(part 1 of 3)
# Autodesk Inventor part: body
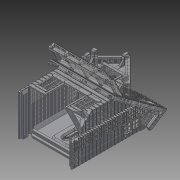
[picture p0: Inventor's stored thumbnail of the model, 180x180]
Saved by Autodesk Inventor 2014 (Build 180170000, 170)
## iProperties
Created: 2013-07
Part Number: body
Material: Generic
Document SubType Name: Modeling
Designer: Brent J. Rosenburgh
Density: 1 g/cm^3
Appearance: Default
Author: Brent J. Rosenburgh
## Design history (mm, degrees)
sketch "Sketch1"
  geometry: L1 (0, 0)-(-140, 0); L2 (-140, 0)-(-140, -200); L3 (-140, -200)-(0, -200); L4 (0, -200)-(0, 0)
  constraints: 8 end point, 2 parallel, 1 horizontal, 1 perpendicular
extrude "Extrusion1" new body sketch "Sketch1" distance "d1" = 140; taper "d2" = 0 deg
sketch "Sketch2"
  geometry: L1 (0, 0)-(0, 200) reference; L2 (0, 200)-(-140, 200) reference; L3 (-140, 0)-(-140, 200) reference; L4 (-22, 200)-(0, 166); L5 (-22, 200)-(-88, 108); L6 (-88, 108)-(-140, 84)
  constraints: 6 end point, 3 point on line
extrude "Extrusion2" cut sketch "Sketch2" distance "d3" = 140; taper "d4" = 0 deg
sketch "Sketch3"
  geometry: L1 (52, 108)-(0, 84) reference; L2 (0, 0)-(0, 84) reference; L3 (140, 0)-(0, 0) reference; L4 (0, 84)-(4, 75.333); L5 (4, 75.333)-(48.778, 96); L6 (48.778, 96)-(48.778, 10); L7 (48.778, 10)-(0, 10); 1 further point
  constraints: 8 end point, 4 perpendicular, 1 point on line
extrude "Extrusion3" cut sketch "Sketch3" distance "d5" = 140; taper "d6" = 0 deg
sketch "Sketch4"
  geometry: L1 (48.778, 10)-(0, 10) reference; L2 (0, 0)-(0, 10) reference; L3 (140, 0)-(0, 0) reference; L4 (140, 0)-(140, 166) reference; L5 (140, 166)-(118, 200) reference; L6 (118, 200)-(52, 108) reference; L7 (48.778, 96)-(48.778, 10) reference; L8 (140, 149.481)-(117.478, 184.288); L9 (117.478, 184.288)-(48.778, 88.524); 1 further point
  constraints: 4 end point, 2 parallel, 2 point on line
extrude "Extrusion4" cut sketch "Sketch4" distance "d7" = 126; taper "d8" = 0 deg
sketch "Sketch5"
  geometry: L1 (140, 10)-(91.222, 10) reference; L2 (91.222, 10)-(91.222, 96) reference; L3 (88, 108)-(22, 200) reference; L4 (22, 200)-(0, 166) reference; L5 (0, 166)-(0, 0) reference; L6 (0, 0)-(140, 0) reference; L7 (140, 10)-(140, 0) reference; L8 (0, 149.465)-(22.527, 184.279); L9 (22.527, 184.279)-(91.222, 88.522); 1 further point
  constraints: 4 end point, 2 parallel, 2 point on line
extrude "Extrusion5" cut sketch "Sketch5" distance "d9" = 10; taper "d10" = 0 deg
sketch "Sketch6"
  geometry: L1 (0, 10)-(48.778, 10) reference; L2 (0, 0)-(0, 10) reference; L3 (140, 0)-(0, 0) reference; L4 (140, 149.481)-(140, 0) reference; L5 (117.478, 184.288)-(140, 149.481) reference; L6 (48.778, 10)-(136, 10); L7 (136, 10)-(136, 155.663); 1 further point
  constraints: 4 end point, 2 perpendicular, 1 point on line
  dimensions: "d11" = 87.222 distance of L1.end L6.end
extrude "Extrusion6" join sketch "Sketch6" distance "d12" = 116; taper "d13" = 0 deg
sketch "Sketch7"
  geometry: L1 (136, 10)-(0, 10) reference; L2 (136, 155.663)-(136, 10) reference; L3 (136, 10)-(48.778, 10); L4 (48.778, 10)-(48.778, 93); L5 (48.778, 93)-(118, 189); L6 (118, 189)-(136, 163); L7 (136, 163)-(136, 155.663); L8 (136, 155.663)-(136, 10); 1 further point
  constraints: 12 end point, 3 perpendicular, 1 point on line
  dimensions: "d14" = 87.222 distance of L1.start L3.end
extrude "Extrusion7" join sketch "Sketch7" distance "d15" = 4; taper "d16" = 0 deg
sketch "Sketch8"
  geometry: L1 (-88, -41.481)-(-140, -65.481) reference; L2 (-140, -65.481)-(-136, -74.148) reference; L3 (-136, -74.148)-(-91.222, -53.481) reference; L4 (-91.222, -60.958)-(-22.522, 34.807) reference; L5 (-88, -41.481)-(-99.275, -57.198); 1 further point
  constraints: 2 end point, 1 parallel, 1 point on line
extrude "Extrusion8" cut sketch "Sketch8" distance "d17" = 16; taper "d18" = 0 deg
sketch "Sketch9"
  geometry: L1 (91.222, -53.465)-(136, -74.131) reference; L2 (136, -74.131)-(140, -65.465) reference; L3 (140, -65.465)-(88, -41.465) reference; L4 (88, -41.465)-(22, 50.535) reference; L5 (88, -41.465)-(99.275, -57.181); 1 further point
  constraints: 2 end point, 1 collinear, 1 point on line
extrude "Extrusion9" cut sketch "Sketch9" distance "d19" = 16; taper "d20" = 0 deg
sketch "Sketch10"
  geometry: L1 (22.527, 34.814)-(91.222, -60.943) reference; L2 (91.222, -60.943)-(91.222, -53.465) reference; L3 (91.222, -53.465)-(99.275, -57.181) reference; L4 (99.275, -57.181)-(105.601, -66); L5 (91.222, -60.943)-(98.503, -71.092); L6 (98.503, -71.092)-(105.601, -66); 1 further point
  constraints: 6 end point, 2 parallel
extrude "Extrusion10" join sketch "Sketch10" distance "d21" = 140; taper "d22" = 0 deg
sketch "Sketch11"
  geometry: L1 (0, 140)-(0, 0) reference; L2 (120, 140)-(120, 0) reference; L3 (0, 140)-(120, 140) reference; L4 (0, 91)-(13, 91); L5 (13, 91)-(13, 133); L6 (120, 91)-(107, 91); L7 (107, 91)-(107, 133); L8 (107, 133)-(13, 133); 1 further point
  constraints: 10 end point, 3 perpendicular, 2 parallel, 2 point on line
extrude "Extrusion11" cut sketch "Sketch11" distance "d23" = 10; taper "d24" = 0 deg
sketch "Sketch12"
  geometry: L1 (13, 0)-(0, 0) reference; L2 (13, 10)-(13, 0) reference; L3 (13, 10)-(9, 10) reference; L4 (0, 10)-(9, 10) reference; L5 (0, 0)-(0, 10) reference; 1 further point
extrude "Extrusion12" join sketch "Sketch12" distance "d25" = 0.22222; taper "d26" = 0 deg
sketch "Sketch13"
  geometry: L1 (13, 0)-(0, 0) reference; L2 (13, 0)-(13, 10) reference; L3 (4, 10)-(13, 10) reference; L4 (4, 10)-(0, 10) reference; L5 (0, 0)-(0, 10) reference; 1 further point
extrude "Extrusion13" join sketch "Sketch13" distance "d27" = 0.22222; taper "d28" = 0 deg
sketch "Sketch14"
  geometry: L1 (38, 139)-(74, 139); L2 (74, 139)-(74, 103); L3 (74, 103)-(38, 103); L4 (38, 103)-(38, 139); L5 (38, 139)-(74, 103); L6 (74, 139)-(38, 103); 2 further points
  constraints: 12 end point, 2 midpoint, 2 parallel, 1 horizontal, 1 perpendicular
extrude "Extrusion14" cut sketch "Sketch14" distance "d29" = 127.97222; taper "d30" = 0 deg
sketch "Sketch15"
  geometry: L1 (36, 0)-(36, -10.75) reference; L2 (0, -10.75)-(-16, -10.75); L3 (-16, -10.75)-(-16, 40); L4 (52.035, 40)-(52.035, -10.75); L5 (52.035, -10.75)-(36, -10.75); L6 (36, -10.75)-(36, -5.375); L7 (36, -5.375)-(46.252, -5.375); L8 (46.252, -5.375)-(46.252, 40); L9 (46.252, 40)-(52.035, 40); L10 (0, -5.375)-(-10, -5.375); L11 (-10, -5.375)-(-10, 40); L12 (-10, 40)-(-16, 40); L13 (0, -5.375)-(0, -10.75); 1 further point
  constraints: 24 end point, 5 perpendicular, 4 parallel, 1 collinear, 1 midpoint
extrude "Extrusion15" join sketch "Sketch15" distance "d31" = 42; taper "d32" = 0 deg
sketch "Sketch16"
  geometry: L1 (16.035, 0)-(16.035, 42) reference; L2 (0, 0)-(0, 42) reference; L3 (16.035, 35.983)-(-51.983, 35.983); L4 (-51.983, 35.983)-(-51.983, 41.983); L5 (-51.983, 41.983)-(-17.983, 76); L6 (-17.983, 76)-(16.035, 42); L7 (16.035, 35.983)-(16.035, 42); 1 further point
  constraints: 10 end point, 3 perpendicular, 1 collinear, 1 point on line
extrude "Extrusion16" join sketch "Sketch16" distance "d33" = 5.375; taper "d34" = 0 deg
sketch "Sketch17"
  geometry: L1 (62.217, 34.508)-(56.252, 34.508) reference; L2 (62.217, 34.508)-(28.235, 68.508) reference; L3 (28.235, 68.508)-(-5.783, 34.508) reference; L4 (0, 34.508)-(-5.783, 34.508) reference; L5 (0, 34.508)-(28.14, 62.634); L6 (28.14, 62.634)-(56.252, 34.508); 1 further point
  constraints: 4 end point, 1 parallel, 1 perpendicular
extrude "Extrusion17" join sketch "Sketch17" distance "d35" = 52.875; taper "d36" = 0 deg
sketch "Sketch18"
  geometry: L1 (-15.076, -36)-(-25.826, -36) reference; L2 (10.75, 0)-(-15.076, -36) reference; L3 (10.75, 0)-(0, 0) reference; L4 (-20.451, -28.508)-(0, 0) reference; L5 (-20.451, -28.508)-(-20.451, -36); 1 further point
  constraints: 2 end point, 1 midpoint
extrude "Extrusion18" cut sketch "Sketch18" distance "d37" = 10; taper "d38" = 0 deg
sketch "Sketch19"
  geometry: L1 (10.75, 0)-(31.201, -28.508) reference; L2 (0, 0)-(10.75, 0) reference; L3 (25.826, -36)-(0, 0) reference; L4 (25.826, -36)-(36.576, -36) reference; L5 (31.201, -28.508)-(31.201, -36); 1 further point
  constraints: 2 end point, 1 midpoint
extrude "Extrusion19" cut sketch "Sketch19" distance "d39" = 10.25211; taper "d40" = 0 deg
sketch "Sketch20"
  geometry: L1 (9.87, 42)-(14.174, 36) reference; L2 (0, 42)-(9.87, 42) reference; L3 (0, 0)-(0, 42) reference; L4 (0, 0)-(40, 0) reference; L5 (24.924, 36)-(20.62, 42) reference; L6 (14.174, 36)-(40, 0); L7 (9.87, 42)-(-9.5, 69); L8 (-9.5, 69)-(-9.5, 37); L9 (-9.5, 37)-(0, 37); 1 further point
  constraints: 8 end point, 2 perpendicular, 1 collinear, 1 parallel, 1 point on line
extrude "Extrusion20" cut sketch "Sketch20" distance "d41" = 66.7521; taper "d43" = 0 deg; dims "d42" = 7.376, "d44" = 0
sketch "Sketch21"
  geometry: L1 (0, 0)-(56.252, 0) reference; L2 (56.252, 0)-(56.252, 7.384) reference; L3 (56.252, 7.384)-(28.112, 41.999) reference; L4 (28.112, 41.999)-(0, 7.384) reference; L5 (0, 7.384)-(0, 0) reference; 1 further point
extrude "Extrusion21" cut sketch "Sketch21" distance "d45" = 11.2479; taper "d46" = 0 deg
sketch "Sketch22"
  geometry: L1 (-52, 42)-(-51.965, 42) reference; L2 (16.035, 42)-(-17.983, 76) reference; L3 (-17.983, 76)-(-51.965, 42) reference; L4 (-17.994, 64.072)-(-65.969, 16.072); L5 (-17.994, 64.072)-(30.031, 16.072); L6 (16.035, 42)-(36, 22.045); L7 (36, 22.045)-(30.031, 16.072); L8 (-52, 42)-(-71.945, 22.045); L9 (-71.945, 22.045)-(-65.969, 16.072); 1 further point
  constraints: 12 end point, 3 parallel, 3 perpendicular
extrude "Extrusion22" join sketch "Sketch22" distance "d47" = 33.7521; taper "d48" = 0 deg
sketch "Sketch23"
  geometry: L1 (-10.252, 35.841)-(-10.252, 39.402) reference; L2 (-10.252, 35.841)-(17.994, 64.072) reference; L3 (17.994, 64.072)-(46, 36.052) reference; L4 (46, 39.402)-(46, 36.052) reference; L5 (40.954, 47.048)-(46, 39.402) reference; L6 (17.888, 70.126)-(40.954, 47.048) reference; L7 (-5.201, 47.048)-(17.888, 70.126) reference; L8 (-10.252, 39.402)-(-5.201, 47.048) reference; 1 further point
extrude "Extrusion23" cut sketch "Sketch23" distance "d49" = 28.3771; taper "d50" = 0 deg
sketch "Sketch24"
  geometry: L1 (0, 0)-(-26.478, 36.908) reference; L2 (-23.002, 39.402)-(5.375, 39.402) reference; L3 (-26.478, 36.908)-(-26.478, 12); L4 (-26.478, 12)-(-8.609, 12); 1 further point
  constraints: 4 end point, 2 perpendicular, 1 point on line
extrude "Extrusion24" cut sketch "Sketch24" distance "d51" = 83.1271; taper "d53" = 0 deg; dims "d52" = 26.189, "d54" = 0
sketch "Sketch25"
  geometry: L1 (36, 22.045)-(-17.983, 76) reference; L2 (-17.983, 76)-(-51.965, 42) reference; L3 (-52, 42)-(-51.965, 42) reference; L4 (-52, 42)-(-71.945, 22.045) reference; L5 (-71.945, 22.045)-(-65.969, 16.072) reference; L6 (-65.969, 16.072)-(-52, 30.049) reference; L7 (16.035, 30.061)-(30.031, 16.072) reference; L8 (30.031, 16.072)-(36, 22.045) reference; L9 (-52, 30.049)-(-17.994, 64.072); L10 (-17.994, 64.072)-(16.035, 30.061); 1 further point
  constraints: 4 end point, 1 parallel, 1 perpendicular
extrude "Extrusion25" join sketch "Sketch25" distance "d55" = 10; taper "d56" = 0 deg
sketch "Sketch26"
  geometry: L1 (46, -10.75)-(10, -10.75) reference; L2 (24, -10.75)-(24, -72); L3 (32, -10.75)-(32, -72); L4 (32, -72)-(24, -72); 1 further point
  constraints: 6 end point, 2 perpendicular, 2 point on line, 1 parallel
extrude "Extrusion26" join sketch "Sketch26" distance "d57" = 8; taper "d58" = 0 deg
sketch "Sketch27"
  geometry: L1 (57.663, -5)-(51.163, -8) reference; L2 (61.25, 0)-(57.663, -5) reference; L3 (51.163, -8)-(0, -8) reference; L4 (25.582, -8)-(35.339, -15); L5 (35.339, -15)-(36.733, -16); L6 (36.733, -16)-(29.367, -19.4); L7 (29.367, -19.4)-(13.476, -8); L8 (25.582, -8)-(13.476, -8); 1 further point
  constraints: 10 end point, 2 collinear, 2 parallel, 1 midpoint, 1 perpendicular, 1 point on line
extrude "Extrusion27" join sketch "Sketch27" distance "d59" = 7; taper "d60" = 0 deg
sketch "Sketch28"
  geometry: L1 (13.476, -8)-(0, -8) reference; L2 (13.476, -8)-(28.23, -18.584) reference; L3 (35.596, -15.185)-(28.23, -18.584) reference; L4 (35.596, -15.185)-(25.582, -8) reference; L5 (25.582, -8)-(13.476, -8); 1 further point
  constraints: 2 end point, 1 collinear
extrude "Extrusion28" cut sketch "Sketch28" distance "d61" = 1; taper "d62" = 0 deg
sketch "Sketch29"
  geometry: L1 (-17.994, 64.072)-(-52, 30.049) reference; L2 (-36, 35.983)-(0, 35.983) reference; L3 (16.035, 0)-(16.035, 30.061) reference; L4 (16.035, 30.061)-(-17.994, 64.072) reference; L5 (-36, 35.983)-(-46.069, 35.983); L6 (0, 35.983)-(10.11, 35.983); L7 (4.09, 42)-(-40.055, 42); 1 further point
  constraints: 6 end point, 4 point on line, 1 collinear, 1 parallel, 1 perpendicular
extrude "Extrusion29" join sketch "Sketch29" distance "d63" = 2; taper "d64" = 0 deg
sketch "Sketch30"
  geometry: L1 (0, 0)-(44.145, 0) reference; L2 (44.145, 0)-(22.061, 22.072) reference; L3 (22.061, 22.072)-(0, 0) reference; L4 (22.061, 22.072)-(22.072, 0); L5 (19, 0)-(18.99, 19); L6 (25, 0)-(24.99, 19.145); L7 (4, 0)-(3.998, 4); L8 (40, 0)-(39.998, 4.145); 1 further point
  constraints: 10 end point, 8 point on line, 4 parallel, 1 midpoint
extrude "Extrusion30" join sketch "Sketch30" distance "d65" = 1; taper "d66" = 0 deg
sketch "Sketch31"
  geometry: L1 (16, 35.983)-(5.931, 35.983) reference; L2 (16, 0)-(0, 0) reference; L3 (16, 0)-(16, 35.983) reference; L4 (12, 35.983)-(12, 0); 1 further point
  constraints: 2 end point, 2 point on line, 1 perpendicular
extrude "Extrusion31" join sketch "Sketch31" distance "d67" = 1; taper "d68" = 0 deg
sketch "Sketch32"
  geometry: L1 (10.11, 35.983)-(0, 35.983) reference; L2 (0, 0)-(0, 35.983) reference; L3 (16.035, 0)-(0, 0) reference; L4 (4, 35.983)-(4, -5); L5 (4, -5)-(-40, -5); L6 (-40, -5)-(-40, 0); L7 (-40, 0)-(0, 0); 1 further point
  constraints: 8 end point, 2 perpendicular, 2 point on line, 1 collinear, 1 parallel
extrude "Extrusion32" join sketch "Sketch32" distance "d69" = 1; taper "d70" = 0 deg
sketch "Sketch33"
  geometry: L1 (-21, 59.44)-(-15, 59.44); L2 (-15, 59.44)-(-15, 70); L3 (-15, 70)-(-21, 70); L4 (-21, 70)-(-21, 59.44); L5 (-63, 27.075)-(-57, 27.075); L6 (-57, 27.075)-(-57, 17.075); L7 (-57, 17.075)-(-63, 17.075); L8 (-63, 17.075)-(-63, 27.075); L9 (27, 27)-(21, 27); L10 (21, 27)-(21, 16.757); L11 (21, 16.757)-(27, 16.757); L12 (27, 16.757)-(27, 27); 1 further point
  constraints: 24 end point, 6 parallel, 3 horizontal, 3 perpendicular
  dimensions: "d71" = 6 distance of L6.end L7.end; "d72" = 10 distance of L5.end L6.end; "d73" = 6 distance of L11.end L10.end
extrude "Extrusion33" join sketch "Sketch33" distance "d74" = 9; taper "d76" = 0 deg; dims "d75" = 13, "d77" = 0
sketch "Sketch34"
  geometry: L1 (-27, 19.101)-(-21, 25.098) reference; L2 (-27, 19.101)-(-27, 16.757) reference; L3 (-27, 16.757)-(-21, 16.757) reference; L4 (-21, 16.757)-(-21, 25.098) reference; 1 further point
extrude "Extrusion34" join sketch "Sketch34" distance "d78" = 16.5; taper "d79" = 0 deg
sketch "Sketch35"
  geometry: L1 (57, 25.046)-(63, 19.043) reference; L2 (57, 25.046)-(57, 17.075) reference; L3 (57, 17.075)-(63, 17.075) reference; L4 (63, 17.075)-(63, 19.043) reference; 1 further point
extrude "Extrusion35" join sketch "Sketch35" distance "d80" = 16.5; taper "d81" = 0 deg
sketch "Sketch36"
  geometry: L1 (0, 30.049)-(-21.557, 30.049) reference; L2 (0, 0)-(-21.557, 30.049) reference; L3 (0, 0)-(0, 30.049) reference; 1 further point
extrude "Extrusion36" join sketch "Sketch36" distance "d82" = 8; taper "d83" = 0 deg
sketch "Sketch37"
  geometry: L1 (21.566, 30.061)-(0, 30.061) reference; L2 (0, 0)-(0, 30.061) reference; L3 (21.566, 30.061)-(0, 0) reference; 1 further point
extrude "Extrusion37" join sketch "Sketch37" distance "d84" = 8; taper "d85" = 0 deg
sketch "Sketch38"
  geometry: L1 (0, 39.402)-(0, 0) reference; L2 (10.252, 0)-(0, 0) reference; L3 (10.252, 35.983)-(10.252, 0) reference; L4 (10.252, 35.983)-(46.252, 35.983) reference; L5 (46.252, 0)-(46.252, 35.983) reference; L6 (46.252, 0)-(56.252, 0) reference; L7 (56.252, 0)-(56.252, 39.402) reference; L8 (51.206, 47.048)-(56.252, 39.402) reference; L9 (28.14, 70.126)-(51.206, 47.048) reference; L10 (5.051, 47.048)-(28.14, 70.126) reference; L11 (0, 39.402)-(5.051, 47.048) reference; L12 (5.051, 47.048)-(-10.005, 32); L13 (-10.005, 32)-(-10.005, 0); L14 (-10.005, 0)-(0, 0); L15 (51.206, 47.048)-(66.247, 32); L16 (66.247, 32)-(66.247, 0); L17 (66.247, 0)-(56.252, 0); 1 further point
  constraints: 12 end point, 3 perpendicular, 2 collinear, 1 parallel
extrude "Extrusion38" cut sketch "Sketch38" distance "d86" = 56; taper "d87" = 0 deg
sketch "Sketch39"
  geometry: L1 (10, -1.64)-(-9, -1.64) reference; L2 (0, 0)-(10, 0) reference; L3 (0.5, -1.64)-(10, -11); L4 (10, -11)-(10, -1.64); 1 further point
  constraints: 4 end point, 1 midpoint, 1 perpendicular
extrude "Extrusion39" join sketch "Sketch39" distance "d88" = 5; taper "d89" = 0 deg
sketch "Sketch40"
  geometry: L1 (0.5, -1.64)-(10, -11) reference; L2 (0, 0)-(10, 0) reference; L3 (0.5, -1.64)-(9, -1.64); L4 (9, -1.64)-(9, -10.015); 1 further point
  constraints: 4 end point, 1 parallel, 1 perpendicular, 1 point on line
extrude "Extrusion40" cut sketch "Sketch40" distance "d90" = 1; taper "d91" = 0 deg
sketch "Sketch41"
  geometry: L1 (10, -7.972)-(10, 0) reference; L2 (-9, -7.972)-(10, -7.972) reference; L3 (0, -7.972)-(10, -18); L4 (10, -18)-(10, -7.972); L5 (10, -18)-(14, -22.011); L6 (14, -22.011)-(30, 0); L7 (30, 0)-(10, 0); 1 further point
  constraints: 10 end point, 2 perpendicular, 1 collinear, 1 point on line
extrude "Extrusion41" join sketch "Sketch41" distance "d92" = 5; taper "d93" = 0 deg
sketch "Sketch42"
  geometry: L1 (-10, 0)-(-10, -8.341) reference; L2 (-10, -8.341)-(9, -8.341) reference; L3 (-10, 0)-(0, 0) reference; L4 (-0.5, -8.341)-(-15, -23); L5 (-15, -23)-(-31, 0); L6 (-31, 0)-(-10, 0); 1 further point
  constraints: 6 end point, 1 collinear, 1 midpoint
extrude "Extrusion42" join sketch "Sketch42" distance "d94" = 5; taper "d95" = 0 deg
sketch "Sketch43"
  geometry: L1 (10, 0)-(10, -18) reference; L2 (-9, -7.972)-(0, -7.972) reference; L3 (0, -7.972)-(10, -18) reference; L4 (0, -7.972)-(10, -7.972); 1 further point
  constraints: 2 end point, 1 collinear, 1 point on line
extrude "Extrusion43" cut sketch "Sketch43" distance "d96" = 1; taper "d97" = 0 deg
sketch "Sketch44"
  geometry: L1 (-10, -17.945)-(-10, 0) reference; L2 (-10, -17.945)-(-0.5, -8.341) reference; L3 (-0.5, -8.341)-(-10, -8.341); 1 further point
  constraints: 2 end point, 1 perpendicular, 1 point on line
extrude "Extrusion44" cut sketch "Sketch44" distance "d98" = 1; taper "d99" = 0 deg
sketch "Sketch45"
  geometry: L1 (30.031, 16.072)-(36, 22.045) reference; L2 (36, 22.045)-(-17.983, 76) reference; L3 (-17.983, 76)-(-51.965, 42) reference; L4 (-51.965, 42)-(-52, 42) reference; L5 (-52, 42)-(-71.945, 22.045) reference; L6 (-71.945, 22.045)-(-65.969, 16.072) reference; L7 (-67.998, 18.1)-(-17.996, 68.127); L8 (-17.996, 68.127)-(32.057, 18.1); 1 further point
  constraints: 4 end point, 2 perpendicular, 2 point on line
extrude "Extrusion45" join sketch "Sketch45" distance "d100" = 0.5; taper "d101" = 0 deg
sketch "Sketch46"
  geometry: L1 (140, -65.465)-(136, -74.131) reference; L2 (88, -41.465)-(140, -65.465) reference; L3 (99.275, -57.181)-(88, -41.465) reference; L4 (136, -74.131)-(99.275, -57.181) reference; 1 further point
extrude "Extrusion46" join sketch "Sketch46" distance "d102" = 10; taper "d103" = 0 deg
sketch "Sketch47"
  geometry: L1 (-140, -65.481)-(-88, -41.481) reference; L2 (-136, -74.148)-(-140, -65.481) reference; L3 (-99.275, -57.198)-(-136, -74.148) reference; L4 (-88, -41.481)-(-99.275, -57.198) reference; 1 further point
extrude "Extrusion47" join sketch "Sketch47" distance "d104" = 10; taper "d105" = 0 deg
sketch "Sketch48"
  geometry: L1 (-51.965, 42)-(-52, 42) reference; L2 (-52, 42)-(-71.945, 22.045) reference; L3 (-71.945, 22.045)-(-67.998, 18.1) reference; L4 (-51.965, 42)-(-71.928, 22.028); 1 further point
  constraints: 2 end point, 1 perpendicular, 1 point on line
extrude "Extrusion48" cut sketch "Sketch48" distance "d106" = 41.75; taper "d107" = 0 deg
sketch "Sketch49"
  geometry: L1 (22.031, -87.292)-(16.072, -79.962) reference; L2 (124, -79.941)-(118.031, -87.292) reference; L3 (0, -143.421)-(140, -143.421) reference; L4 (36.035, -55.382)-(36.035, -55.643); L5 (36.035, -55.643)-(14.63, -82); L6 (14.63, -82)-(11.481, -74.314); L7 (11.481, -74.314)-(36.035, -44.881); L8 (36.035, -44.881)-(36.035, -55.382); 1 further point
  constraints: 10 end point, 1 collinear, 1 parallel, 1 perpendicular, 1 point on line
extrude "Extrusion49" join sketch "Sketch49" distance "d108" = 8.736; taper "d109" = 0 deg
sketch "Sketch50"
  geometry: L1 (112, 0)-(112, 145.663) reference; L2 (0, 0)-(0, 145.663) reference; L3 (44, 103)-(0, 103); L4 (0, 103)-(0, 98); L5 (0, 98)-(44, 98); L6 (44, 98)-(44, 103); L7 (68, 103)-(112, 103); L8 (112, 103)-(112, 98); L9 (112, 98)-(68, 98); L10 (68, 98)-(68, 103); 1 further point
  constraints: 16 end point, 4 parallel, 2 horizontal, 2 perpendicular, 2 point on line
extrude "Extrusion50" join sketch "Sketch50" distance "d110" = 77.9857; taper "d111" = 0 deg
sketch "Sketch51"
  geometry: L1 (-44, 69.663)-(-44, 0) reference; L2 (-68, 69.663)-(-68, 0) reference; L3 (-38, -11.75)-(-52, -11.75) reference; L4 (-68, 0)-(-93.951, 20.965); L5 (-93.951, 20.965)-(-93.951, 44.954); L6 (-93.951, 44.954)-(-68, 69.663); L7 (-44, 69.663)-(-20.855, 45.354); L8 (-20.855, 45.354)-(-20.855, 22.036); L9 (-20.855, 22.036)-(-44, 0); 1 further point
  constraints: 12 end point, 3 perpendicular, 1 parallel
extrude "Extrusion51" cut sketch "Sketch51" distance "d112" = 5.9857; taper "d113" = 0 deg
sketch "Sketch52"
  geometry: L1 (0, 0)-(0, 5) reference; L2 (-3.587, 0)-(0, 5) reference; L3 (0, 0)-(-3.587, 0) reference; 1 further point
extrude "Extrusion52" join sketch "Sketch52" distance "d114" = 24.9857; taper "d115" = 0 deg
sketch "Sketch53"
  geometry: L1 (4, 0)-(0, 0) reference; L2 (0, -78.522)-(0, 0) reference; L3 (0, -78.522)-(-9, -78.522) reference; L4 (-9, -88.522)-(-9, -78.522) reference; L5 (-9, -88.522)-(4, -88.522) reference; L6 (4, -88.522)-(4, 0) reference; L7 (0, 0)-(0, 13); L8 (0, 13)-(-116, 13); L9 (-116, 13)-(-116, -88.522); L10 (-116, -88.522)-(-9, -88.522); L11 (4, 0)-(4, 13); L12 (4, 13)-(0, 13); 1 further point
  constraints: 12 end point, 3 parallel, 3 perpendicular
extrude "Extrusion53" join sketch "Sketch53" distance "d116" = 3; taper "d117" = 0 deg
sketch "Sketch54"
  geometry: L1 (107, 0)-(120, 0) reference; L2 (116, 0)-(4, 0); L3 (4, 0)-(4, 22); L4 (4, 22)-(116, 22); L5 (116, 22)-(116, 0); 1 further point
  constraints: 8 end point, 2 parallel, 1 horizontal, 1 perpendicular, 1 point on line
extrude "Extrusion54" join sketch "Sketch54" distance "d118" = 44; taper "d119" = 0 deg
sketch "Sketch55"
  geometry: L1 (4, 22)-(116, 22) reference; L2 (60, 22)-(38, 22); L3 (38, 22)-(38, 66); L4 (38, 66)-(60, 66); L5 (60, 66)-(60, 22); L6 (60, 66)-(82, 66); L7 (82, 66)-(82, 22); L8 (82, 22)-(60, 22); L9 (60, 22)-(60, 66); 1 further point
  constraints: 16 end point, 4 parallel, 2 horizontal, 2 perpendicular, 1 midpoint, 1 point on line
extrude "Extrusion55" cut sketch "Sketch55" distance "d120" = 3; taper "d121" = 0 deg
sketch "Sketch56"
  geometry: L1 (48.778, 22)-(49.778, 22); L2 (48.778, 22)-(49.778, 30); L3 (49.778, 30)-(48.778, 30); L4 (48.778, 30)-(49.778, 38); L5 (49.778, 38)-(48.778, 38); L6 (48.778, 38)-(49.778, 46); L7 (49.778, 46)-(48.778, 46); L8 (48.778, 46)-(49.778, 54); L9 (49.778, 54)-(48.778, 54); L10 (48.778, 54)-(49.778, 62); L11 (49.778, 62)-(48.778, 62); L12 (48.778, 62)-(49.778, 70); L13 (49.778, 70)-(48.778, 70); L14 (48.778, 70)-(49.778, 78); L15 (49.778, 78)-(48.778, 78); L16 (48.778, 78)-(49.778, 86); L17 (49.778, 86)-(48.778, 86); 3 further points
  constraints: 34 end point, 9 horizontal, 7 parallel, 10 other
  dimensions: "d122" = 1 distance of L1.start L1.end
extrude "Extrusion56" cut sketch "Sketch56" distance "d123" = 120; taper "d124" = 0 deg
sketch "Sketch57"
  geometry: L1 (48.778, 0)-(48.778, 22) reference; L2 (48.778, 0)-(140, 0) reference; L3 (48.778, 88.524)-(117.478, 184.288) reference; L4 (49.778, 38)-(48.778, 30) reference; L5 (48.778, 30)-(49.778, 30) reference; L6 (48.778, 22)-(49.778, 22); L7 (49.778, 22)-(48.778, 14); L8 (48.778, 14)-(49.778, 13.875); L9 (49.778, 13.875)-(48.778, 5.875); L10 (48.778, 5.875)-(49.778, 5.158); L11 (49.778, 5.158)-(49.778, 0); 1 further point
  constraints: 12 end point, 4 perpendicular, 3 point on line, 2 parallel
extrude "Extrusion57" cut sketch "Sketch57" distance "d125" = 4; taper "d126" = 0 deg
sketch "Sketch58"
  geometry: L1 (91.222, 78)-(90.222, 86) reference; L2 (22.527, 184.279)-(91.222, 88.522) reference; L3 (91.222, 0)-(0, 0) reference; L4 (91.222, 22)-(91.222, 0) reference; L5 (91.222, 22)-(90.222, 22); L6 (90.222, 22)-(91.222, 14); L7 (91.222, 14)-(90.222, 13.875); L8 (90.222, 13.875)-(91.222, 5.875); L9 (91.222, 5.875)-(90.222, 5.158); L10 (90.222, 5.158)-(90.222, 0); 1 further point
  constraints: 12 end point, 5 perpendicular, 3 point on line, 1 parallel
extrude "Extrusion58" cut sketch "Sketch58" distance "d127" = 4; taper "d128" = 0 deg
sketch "Sketch59"
  geometry: L1 (130, -200)-(10, -200) reference; L2 (130, -178)-(129, -178); L3 (129, -178)-(130, -186); L4 (130, -186)-(129, -186.125); L5 (129, -186.125)-(130, -194.125); L6 (130, -194.125)-(129, -195); L7 (129, -195)-(129, -200); L8 (130, -178)-(129, -170); L9 (129, -170)-(130, -170); L10 (130, -170)-(129, -162); L11 (129, -162)-(130, -162); L12 (130, -162)-(129, -154); L13 (129, -154)-(130, -154); L14 (130, -154)-(129, -146); L15 (129, -146)-(130, -146); L16 (130, -146)-(129, -138); L17 (129, -138)-(130, -138); L18 (130, -138)-(129, -130); L19 (129, -130)-(130, -130); L20 (130, -130)-(129, -122); L21 (129, -122)-(130, -122); 2 further points
  constraints: 40 end point, 8 horizontal, 7 parallel, 3 perpendicular, 1 point on line, 11 other
extrude "Extrusion59" cut sketch "Sketch59" distance "d129" = 92; taper "d130" = 0 deg
sketch "Sketch60"
  geometry: L1 (129, -195)-(130, -194.125) reference; L2 (129, -200)-(10, -200) reference; L3 (10, -178)-(11, -178); L4 (11, -178)-(10, -186); L5 (10, -186)-(11, -186.125); L6 (11, -186.125)-(10, -194.125); L7 (10, -194.125)-(10.626, -194.84); L8 (10.626, -194.84)-(10.626, -200); L9 (10, -178)-(11, -170); L10 (11, -170)-(10, -170); L11 (10, -170)-(11, -162); L12 (11, -162)-(10, -162); L13 (10, -162)-(11, -154); L14 (11, -154)-(10, -154); L15 (10, -154)-(11, -146); L16 (11, -146)-(10, -146); L17 (10, -146)-(11, -138); L18 (11, -138)-(10, -138); L19 (10, -138)-(11, -130); L20 (11, -130)-(10, -130); L21 (10, -130)-(11, -122); L22 (11, -122)-(10, -122); 2 further points
  constraints: 40 end point, 8 horizontal, 7 parallel, 4 perpendicular, 1 point on line, 11 other
extrude "Extrusion60" cut sketch "Sketch60" distance "d131" = 92; taper "d132" = 0 deg
sketch "Sketch61"
  geometry: L1 (130, -130)-(129, -122) reference; L2 (130, -122)-(130, -50.535) reference; L3 (10, -122)-(10, -50.519) reference; L4 (10, -122)-(11, -114); L5 (11, -114)-(10, -114); L6 (130, -122)-(129, -114); L7 (129, -114)-(130, -114); 1 further point
  constraints: 8 end point, 2 perpendicular, 2 point on line, 1 parallel
extrude "Extrusion61" cut sketch "Sketch61" distance "d133" = 92; taper "d134" = 0 deg
sketch "Sketch62"
  geometry: L1 (130, -122)-(129, -114) reference; L2 (10, -114)-(11, -106); L3 (11, -106)-(10, -106); L4 (10, -106)-(11, -98); L5 (11, -98)-(10, -98); L6 (10, -98)-(11, -90); L7 (11, -90)-(10, -90); L8 (10, -90)-(11, -82); L9 (11, -82)-(10, -82); L10 (10, -82)-(11, -74); L11 (11, -74)-(10, -74); L12 (10, -74)-(11, -66); L13 (11, -66)-(10, -66); L14 (10, -66)-(11, -58); L15 (11, -58)-(10, -58); L16 (10, -58)-(10.935, -50.519); L17 (130, -114)-(129, -106); L18 (129, -106)-(130, -106); L19 (130, -106)-(128.998, -98); L20 (128.998, -98)-(130, -98); L21 (130, -98)-(128.998, -90.001); L22 (128.998, -90.001)-(130, -90.001); L23 (130, -90.001)-(128.998, -82.001); L24 (128.998, -82.001)-(130, -82.001); L25 (130, -82.001)-(128.998, -74.001); L26 (128.998, -74.001)-(130, -74.001); L27 (130, -74.001)-(128.998, -66.001); L28 (128.998, -66.001)-(130, -66.001); L29 (130, -66.001)-(128.997, -58); L30 (128.997, -58)-(130, -58); L31 (130, -58)-(129.065, -50.535); L32 (129.065, -50.535)-(130, -50.535); L33 (10.935, -50.519)-(10, -50.519); 1 further point; 2 other entities
  constraints: 64 end point, 15 horizontal, 15 parallel, 16 other
extrude "Extrusion62" cut sketch "Sketch62" distance "d135" = 92; taper "d136" = 0 deg
sketch "Sketch63"
  geometry: L1 (-4, 6)-(0, 4.154) reference; L2 (-5.435, 8)-(-4, 6) reference; L3 (-16.185, 8)-(-5.435, 8) reference; L4 (-10.446, 0)-(-16.185, 8) reference; L5 (-10.446, 0)-(0, 0) reference; L6 (0, 0)-(0, 4.154) reference; 1 further point
extrude "Extrusion63" join sketch "Sketch63" distance "d137" = 1; taper "d138" = 0 deg
sketch "Sketch64"
  geometry: L1 (16.186, 8)-(10.447, 0) reference; L2 (16.186, 8)-(5.434, 8) reference; L3 (4, 6)-(5.434, 8) reference; L4 (0, 4.154)-(4, 6) reference; L5 (0, 4.154)-(0, 0) reference; L6 (10.447, 0)-(0, 0) reference; 1 further point
extrude "Extrusion64" join sketch "Sketch64" distance "d139" = 1; taper "d140" = 0 deg
sketch "Sketch65"
  geometry: L1 (-22, 50.519)-(-105.601, -66.016) reference; L2 (-105.601, -66.016)-(-98.503, -71.108) reference; L3 (-98.503, -71.108)-(-91.222, -60.959) reference; L4 (-91.222, -60.959)-(-91.222, -60.958) reference; L5 (-91.222, -60.958)-(-22.522, 34.807) reference; L6 (-22.522, 34.807)-(0, 0) reference; L7 (0, 0)-(0, 16.519) reference; L8 (0, 16.519)-(-22, 50.519) reference; 1 further point
extrude "Extrusion65" join sketch "Sketch65" distance "d141" = 12.25; taper "d142" = 0 deg
sketch "Sketch66"
  geometry: L1 (105.601, -66)-(22, 50.535) reference; L2 (22, 50.535)-(0, 16.535) reference; L3 (0, 16.535)-(0, 0) reference; L4 (0, 0)-(22.527, 34.814) reference; L5 (22.527, 34.814)-(98.503, -71.092) reference; L6 (98.503, -71.092)-(105.601, -66) reference; 1 further point
extrude "Extrusion66" join sketch "Sketch66" distance "d143" = 12.25; taper "d144" = 0 deg
sketch "Sketch67"
  geometry: L1 (0, 149.465)-(47.502, 149.465) reference; L2 (22.527, 184.279)-(47.502, 149.465) reference; L3 (0, 149.465)-(22.527, 184.279) reference; L4 (42, 157.135)-(4.963, 157.135); 1 further point
  constraints: 2 end point, 2 point on line, 1 parallel
extrude "Extrusion67" join sketch "Sketch67" distance "d145" = 1; taper "d146" = 0 deg
sketch "Sketch68"
  geometry: L1 (92.508, 149.481)-(140, 149.481) reference; L2 (117.478, 184.288)-(140, 149.481) reference; L3 (92.508, 149.481)-(117.478, 184.288) reference; L4 (98, 157.136)-(135.047, 157.136); 1 further point
  constraints: 2 end point, 2 point on line, 1 parallel
extrude "Extrusion68" join sketch "Sketch68" distance "d147" = 1; taper "d148" = 0 deg
sketch "Sketch69"
  geometry: L1 (98, 157.136)-(135.047, 157.136) reference; L2 (117.478, 184.288)-(135.047, 157.136) reference; L3 (98, 157.136)-(117.478, 184.288) reference; L4 (114, 179.439)-(114, 157.136); L5 (120.615, 179.439)-(120.615, 157.136); L6 (131, 163.39)-(131, 157.136); L7 (102.486, 163.39)-(102.486, 157.136); 1 further point
  constraints: 8 end point, 8 point on line, 4 perpendicular
extrude "Extrusion69" join sketch "Sketch69" distance "d149" = 0.5; taper "d150" = 0 deg
sketch "Sketch70"
  geometry: L1 (4.963, 157.135)-(42, 157.135) reference; L2 (22.527, 184.279)-(42, 157.135) reference; L3 (4.963, 157.135)-(22.527, 184.279) reference; L4 (19.357, 179.38)-(19.357, 157.135); L5 (26, 157.135)-(26, 179.438); L6 (37.475, 163.443)-(37.475, 157.135); L7 (9.045, 163.443)-(9.045, 157.135); 1 further point
  constraints: 8 end point, 8 point on line, 2 parallel, 2 perpendicular
extrude "Extrusion70" join sketch "Sketch70" distance "d151" = 0.5; taper "d152" = 0 deg
sketch "Sketch71"
  geometry: L1 (0, 0)-(-8.424, -4.272) reference; L2 (0, 0)-(0, 21.53) reference; L3 (-8.424, 22.03)-(-2.868, 22.03) reference; L4 (0, 19)-(-5.646, 13.409); L5 (-5.646, 13.409)-(-5.646, -2.863); 1 further point
  constraints: 4 end point, 2 point on line, 1 perpendicular
extrude "Extrusion71" cut sketch "Sketch71" distance "d153" = 4; taper "d154" = 0 deg
sketch "Sketch72"
  geometry: L1 (25.815, 8.444)-(21.53, 0) reference; L2 (21.53, 0)-(0, 0) reference; L3 (3.451, 0)-(9, 5.655); L4 (9, 5.655)-(24.4, 5.655); 1 further point
  constraints: 4 end point, 2 point on line, 1 parallel
extrude "Extrusion72" cut sketch "Sketch72" distance "d155" = 4; taper "d156" = 0 deg
sketch "Sketch73"
  geometry: L1 (0, 0)-(140, 0) reference; L2 (0, 8.736)-(140, 8.736) reference; L3 (0, 0)-(0, 8.736) reference; L4 (3, 0)-(3, 6); L5 (3, 6)-(137.262, 6); L6 (137.262, 6)-(137.262, 0); 1 further point
  constraints: 6 end point, 2 parallel, 2 point on line, 1 perpendicular
extrude "Extrusion73" cut sketch "Sketch73" distance "d157" = 12.5; taper "d158" = 0 deg
sketch "Sketch74"
  geometry: L1 (9.5, 0)-(0, 0) reference; L2 (0, 0)-(0, -5.958) reference; L3 (0, -5.958)-(-0.5, -5.958) reference; L4 (-0.5, -5.958)-(-0.5, -25.644) reference; L5 (-0.5, -25.644)-(0, -25.644) reference; L6 (0, -25.644)-(0, -33.407) reference; L7 (0, -33.407)-(0.5, -33.407) reference; L8 (0.5, -33.407)-(0.5, -42.846) reference; L9 (-1.435, -42.846)-(0.5, -42.846) reference; L10 (-0.5, -52.033)-(-1.435, -42.846) reference; L11 (-1.503, -52.033)-(-0.5, -52.033) reference; L12 (-0.5, -61.881)-(-1.503, -52.033) reference; L13 (-1.502, -61.881)-(-0.5, -61.881) reference; L14 (-0.5, -71.726)-(-1.502, -61.881) reference; L15 (-1.502, -71.726)-(-0.5, -71.726) reference; L16 (-0.5, -81.572)-(-1.502, -71.726) reference; L17 (-1.502, -81.572)-(-0.5, -81.572) reference; L18 (-0.5, -91.417)-(-1.502, -81.572) reference; L19 (-1.502, -91.417)-(-0.5, -91.417) reference; L20 (-0.5, -101.262)-(-1.502, -91.417) reference; L21 (-1.502, -101.262)-(-0.5, -101.262) reference; L22 (-0.5, -111.108)-(-1.502, -101.262) reference; L23 (-1.5, -111.108)-(-0.5, -111.108) reference; L24 (-0.816, -117.84)-(-1.5, -111.108) reference; L25 (-0.816, -117.84)-(6.5, -117.84) reference; L26 (6.5, -117.84)-(6.5, 0); 1 further point
  constraints: 2 end point, 1 perpendicular, 1 point on line
extrude "Extrusion74" cut sketch "Sketch74" distance "d159" = 6; taper "d160" = 0 deg
sketch "Sketch75"
  geometry: L1 (9.5, 9.136)-(9.5, 16.649) reference; L2 (9.5, 16.649)-(10, 16.649) reference; L3 (10, 16.649)-(10, 35.631) reference; L4 (10, 35.631)-(9.5, 35.631) reference; L5 (9.5, 35.631)-(9.5, 41.467) reference; L6 (3, 41.467)-(9.5, 41.467) reference; L7 (9, 0)-(0, 0) reference; L8 (9, 0)-(9, 9.136) reference; L9 (9, 9.136)-(9.5, 9.136) reference; L10 (3, 41.467)-(3, 0); 1 further point
  constraints: 2 end point, 1 perpendicular, 1 point on line
extrude "Extrusion75" cut sketch "Sketch75" distance "d161" = 6; taper "d162" = 0 deg
sketch "Sketch76"
  geometry: L1 (2.738, -117.85)-(10.316, -117.85) reference; L2 (11, -111.118)-(10.316, -117.85) reference; L3 (10, -111.118)-(11, -111.118) reference; L4 (11, -101.272)-(10, -111.118) reference; L5 (10, -101.272)-(11, -101.272) reference; L6 (11, -91.427)-(10, -101.272) reference; L7 (10, -91.427)-(11, -91.427) reference; L8 (11, -81.581)-(10, -91.427) reference; L9 (10, -81.581)-(11, -81.581) reference; L10 (11, -71.735)-(10, -81.581) reference; L11 (10, -71.735)-(11, -71.735) reference; L12 (11, -61.89)-(10, -71.735) reference; L13 (10, -61.89)-(11, -61.89) reference; L14 (11, -52.044)-(10, -61.89) reference; L15 (10, -52.044)-(11, -52.044) reference; L16 (10.935, -42.837)-(10, -52.044) reference; L17 (10.935, -42.837)-(9, -42.837) reference; L18 (9, -42.837)-(9, -33.415) reference; L19 (9, -33.415)-(9.5, -33.415) reference; L20 (9.5, -33.415)-(9.5, -25.719) reference; L21 (9.5, -25.719)-(10, -25.719) reference; L22 (10, -25.719)-(10, -5.967) reference; L23 (10, -5.967)-(9.5, -5.967) reference; L24 (9.5, -5.967)-(9.5, 0) reference; L25 (0, 0)-(9.5, 0) reference; L26 (0, -117.858)-(0, 0) reference; L27 (2.738, -117.858)-(0, -117.858) reference; L28 (2.738, -117.858)-(2.738, -117.85) reference; L29 (2.738, -117.858)-(2.738, 0); 1 further point
  constraints: 2 end point, 1 perpendicular, 1 point on line
extrude "Extrusion76" cut sketch "Sketch76" distance "d163" = 6; taper "d164" = 0 deg
sketch "Sketch77"
  geometry: L1 (-0.5, 16.567)-(-0.5, 9.118) reference; L2 (-0.5, 9.118)-(0, 9.118) reference; L3 (0, 9.118)-(0, 0) reference; L4 (9, 0)-(0, 0) reference; L5 (6.262, 41.458)-(-0.5, 41.458) reference; L6 (-0.5, 41.458)-(-0.5, 35.683) reference; L7 (-0.5, 35.683)-(-1, 35.683) reference; L8 (-1, 35.683)-(-1, 16.567) reference; L9 (-1, 16.567)-(-0.5, 16.567) reference; L10 (6.262, 41.458)-(6.262, 0); 1 further point
  constraints: 2 end point, 1 perpendicular, 1 point on line
extrude "Extrusion77" cut sketch "Sketch77" distance "d165" = 6; taper "d166" = 0 deg
sketch "Sketch78"
  geometry: L1 (-22, 50.519)-(-105.601, -66.016) reference; L2 (-105.601, -66.016)-(-98.503, -71.108) reference; L3 (0, 0)-(0, 16.519) reference; L4 (0, 16.519)-(-22, 50.519) reference; L5 (-100, -70.035)-(-22, 38.693); L6 (-22, 38.693)-(0, 4.693); 1 further point
  constraints: 4 end point, 2 parallel, 2 point on line
extrude "Extrusion78" join sketch "Sketch78" distance "d167" = 0.5; taper "d168" = 0 deg
sketch "Sketch79"
  geometry: L1 (105.601, -66)-(22, 50.535) reference; L2 (22, 50.535)-(0, 16.535) reference; L3 (0, 16.535)-(0, 0) reference; L4 (0, 0)-(22.527, 34.814) reference; L5 (98.503, -71.092)-(105.601, -66) reference; L6 (100.026, -70)-(22.527, 38.028); L7 (22.527, 38.028)-(0, 3.214); 1 further point
  constraints: 4 end point, 2 parallel, 2 point on line
extrude "Extrusion79" join sketch "Sketch79" distance "d169" = 0.5; taper "d170" = 0 deg
sketch "Sketch80"
  geometry: L1 (128, 0)-(0, 0) reference; L2 (3, 0)-(125, 0); L3 (125, 0)-(125, 7); L4 (125, 7)-(3, 7); L5 (3, 7)-(3, 0); 1 further point
  constraints: 8 end point, 2 parallel, 1 horizontal, 1 perpendicular, 1 point on line
extrude "Extrusion80" cut sketch "Sketch80" distance "d171" = 40.5; taper "d172" = 0 deg
sketch "Sketch81"
  geometry: L1 (0.001, 12.492)-(0.001, 130.35) reference; L2 (0, 12.491)-(0.001, 12.492) reference; L3 (0, 0)-(0, 12.491) reference; L4 (6, 0)-(0, 0) reference; L5 (6, 0)-(6, 12.5) reference; L6 (6, 12.5)-(6.001, 12.5) reference; L7 (6.001, 12.5)-(6.001, 130.35) reference; L8 (6.001, 130.35)-(0.001, 130.35) reference; L9 (6, 0)-(6, -8); L10 (6, -8)-(0, -8); L11 (0, -8)-(0, 0); 1 further point
  constraints: 6 end point, 2 perpendicular, 1 parallel
extrude "Extrusion81" join sketch "Sketch81" distance "d173" = 3; taper "d174" = 0 deg
sketch "Sketch82"
  geometry: L1 (6, 0)-(0, 0) reference; L2 (6, 130.34)-(6, 0) reference; L3 (6, 130.34)-(0, 130.34) reference; L4 (0, 0)-(0, 130.34) reference; L5 (0, -8)-(6, -8); L6 (6, -8)-(6, 0); L7 (6, 0)-(0, 0); L8 (0, 0)-(0, -8); 1 further point
  constraints: 8 end point, 2 parallel, 1 horizontal, 1 perpendicular
extrude "Extrusion82" join sketch "Sketch82" distance "d175" = 3; taper "d176" = 0 deg
sketch "Sketch83"
  geometry: L1 (-46.069, 35.983)-(10.11, 35.983) reference; L2 (4.09, 42)-(10.11, 35.983) reference; L3 (4.09, 42)-(-40.055, 42) reference; L4 (-46.069, 35.983)-(-40.055, 42) reference; 1 further point
extrude "Extrusion83" join sketch "Sketch83" distance "d177" = 1; taper "d178" = 0 deg
sketch "Sketch84"
  geometry: L1 (12, 35.983)-(16, 35.983) reference; L2 (12, 35.983)-(12, -1.394) reference; L3 (30, -1.394)-(12, -1.394) reference; L4 (30, 0)-(30, -1.394) reference; L5 (30, 0)-(16, 0) reference; L6 (16, 0)-(16, 35.983) reference; 1 further point
extrude "Extrusion84" join sketch "Sketch84" distance "d179" = 1; taper "d180" = 0 deg
sketch "Sketch85"
  geometry: L1 (4, -1.394)-(-14, -1.394) reference; L2 (4, -1.394)-(4, 35.983) reference; L3 (0, 35.983)-(4, 35.983) reference; L4 (0, 35.983)-(0, 0) reference; L5 (0, 0)-(-14, 0) reference; L6 (-14, -1.394)-(-14, 0) reference; 1 further point
extrude "Extrusion85" join sketch "Sketch85" distance "d181" = 1; taper "d182" = 0 deg
sketch "Sketch86"
  geometry: L1 (0, 0)-(0, 35.983) reference; L2 (1, -1.394)-(0, 0) reference; L3 (0, 35.983)-(1, 28); L4 (1, 28)-(0, 28); L5 (0, 28)-(1, 20.017); L6 (1, 20.017)-(0, 20.017); L7 (0, 20.017)-(1, 12.035); L8 (1, 12.035)-(0, 12.035); L9 (0, 12.035)-(1, 4.052); L10 (1, 4.052)-(0, 4.052); L11 (0, 4.052)-(1, -1.394); 1 further point
  constraints: 18 end point, 4 perpendicular, 4 point on line, 3 parallel
extrude "Extrusion86" join sketch "Sketch86" distance "d183" = 20; taper "d184" = 0 deg
sketch "Sketch87"
  geometry: L1 (2.02, -2.021)-(0, 0) reference; L2 (2.02, 0)-(2.02, -2.021) reference; L3 (0, 0)-(2.02, 0) reference; 1 further point
extrude "Extrusion87" cut sketch "Sketch87" distance "d185" = 1; taper "d186" = 0 deg
sketch "Sketch88"
  geometry: L1 (0, 0)-(-1, -1.394) reference; L2 (0, 35.983)-(0, 0) reference; L3 (0, 35.983)-(-1, 28); L4 (-1, 28)-(0, 28); L5 (0, 28)-(-1, 20.017); L6 (-1, 20.017)-(0, 20.017); L7 (0, 20.017)-(-1, 12.035); L8 (-1, 12.035)-(0, 12.035); L9 (0, 12.035)-(-1, 4.052); L10 (-1, 4.052)-(0, 4.052); L11 (0, 4.052)-(-1, -1.394); 1 further point
  constraints: 18 end point, 4 perpendicular, 4 point on line, 3 parallel
extrude "Extrusion88" join sketch "Sketch88" distance "d187" = 20.03468; taper "d188" = 0 deg
sketch "Sketch89"
  geometry: L1 (1.98, 0)-(0, -1.979) reference; L2 (1.98, 0)-(0, 0) reference; L3 (0, -1.979)-(0, 0) reference; 1 further point
extrude "Extrusion89" cut sketch "Sketch89" distance "d189" = 1; taper "d190" = 0 deg
sketch "Sketch90"
  geometry: L1 (116, 0)-(116, 22) reference; L2 (116, 22)-(4, 22) reference; L3 (4, 22)-(4, 0) reference; L4 (4, 0)-(116, 0) reference; 1 further point
extrude "Extrusion90" cut sketch "Sketch90" distance "d191" = 135.25; taper "d192" = 0 deg
sketch "Sketch91"
  geometry: L1 (26, -22.522)-(8, -22.522); L2 (8, -22.522)-(8, -55); L3 (8, -55)-(26, -55); L4 (26, -55)-(26, -22.522); L5 (86, -22.522)-(104, -22.522); L6 (104, -22.522)-(104, -55); L7 (104, -55)-(86, -55); L8 (86, -55)-(86, -22.522); 1 further point
  constraints: 16 end point, 4 parallel, 2 horizontal, 2 perpendicular
extrude "Extrusion91" cut sketch "Sketch91" distance "d193" = 4.5; taper "d194" = 0 deg
sketch "Sketch92"
  geometry: L1 (4, 33)-(-13, 33); L2 (-13, 33)-(-13, 57); L3 (-13, 57)-(4, 57); L4 (4, 57)-(4, 33); 1 further point
  constraints: 8 end point, 2 parallel, 1 horizontal, 1 perpendicular
extrude "Extrusion92" cut sketch "Sketch92" distance "d195" = 49.25; taper "d196" = 0 deg
sketch "Sketch93"
  geometry: L1 (-13, -57)-(4, -57) reference; L2 (-1.532, -57)-(4, -57); L3 (4, -57)-(4, -33); L4 (4, -33)-(-1.532, -33); L5 (-1.532, -33)-(-1.532, -57); 1 further point
  constraints: 8 end point, 2 parallel, 1 horizontal, 1 perpendicular, 1 point on line
extrude "Extrusion93" join sketch "Sketch93" distance "d197" = 144.25; taper "d198" = 0 deg
sketch "Sketch94"
  geometry: L1 (4, -57)-(-16, -57); L2 (-16, -57)-(-16, -30); L3 (-16, -30)-(4, -30); L4 (4, -30)-(4, -57); 1 further point
  constraints: 8 end point, 2 parallel, 1 horizontal, 1 perpendicular
extrude "Extrusion94" join sketch "Sketch94" distance "d199" = 3; taper "d200" = 0 deg
sketch "Sketch95"
  geometry: L1 (1.935, -30)-(6, -30); L2 (6, -30)-(6, -57); L3 (6, -57)-(1.935, -57); L4 (1.935, -33)-(1.935, -30) reference; L5 (1.935, -30)-(-1, -30); L6 (-1, -30)-(-1, -52); L7 (-1, -52)-(1.935, -57); 1 further point
  constraints: 12 end point, 3 perpendicular, 1 horizontal, 1 parallel
extrude "Extrusion95" join sketch "Sketch95" distance "d201" = 141.25; taper "d202" = 0 deg
sketch "Sketch96"
  geometry: L1 (5.197, -54.876)-(4, -54.876) reference; L2 (5.197, -47.492)-(5.197, -54.876) reference; L3 (6, -47.492)-(5.197, -47.492) reference; L4 (6, -30)-(6, -47.492) reference; L5 (6, -30)-(1.935, -30) reference; L6 (1.935, -33)-(1.935, -30) reference; L7 (4, -54.876)-(4, -33); L8 (4, -33)-(1.935, -33); 1 further point
  constraints: 4 end point, 1 parallel, 1 perpendicular
extrude "Extrusion96" join sketch "Sketch96" distance "d203" = 36; taper "d204" = 0 deg
sketch "Sketch97"
  geometry: L1 (-2.124, 4.692)-(0, 1.731) reference; L2 (-2.124, 4.692)-(-2.124, 36) reference; L3 (-24, 36)-(-2.124, 36) reference; L4 (-24, 0)-(-24, 36) reference; L5 (-2.124, 4.692)-(-24, 35.186); 1 further point
  constraints: 2 end point, 1 collinear, 1 point on line
extrude "Extrusion97" cut sketch "Sketch97" distance "d205" = 4.75; taper "d206" = 0 deg
sketch "Sketch98"
  geometry: L1 (0, 0)-(3, 0) reference; L2 (3, 0)-(3, 22.839) reference; L3 (0, 27.02)-(3, 22.839) reference; L4 (0, 0)-(0, 27.02) reference; 1 further point
extrude "Extrusion98" join sketch "Sketch98" distance "d207" = 2; taper "d208" = 0 deg
sketch "Sketch99"
  geometry: L1 (0, 0)-(-0.584, 0.814) reference; L2 (0, 0)-(0, 0.814) reference; L3 (-0.584, 0.814)-(0, 0.814) reference; 1 further point
extrude "Extrusion99" cut sketch "Sketch99" distance "d209" = 5.25; taper "d210" = 0 deg
sketch "Sketch100"
  geometry: L1 (-3.065, -30)-(-3.065, -33) reference; L2 (-3.065, -30)-(-16, -30) reference; L3 (-16, -30)-(-16, -47.492) reference; L4 (-13, -47.492)-(-16, -47.492) reference; L5 (4, -57)-(4, -33) reference; L6 (-3.065, -33)-(-13, -33); L7 (-13, -33)-(-13, -47.492); 1 further point
  constraints: 4 end point, 2 perpendicular
extrude "Extrusion100" join sketch "Sketch100" distance "d211" = 27; taper "d212" = 0 deg
sketch "Sketch101"
  geometry: L1 (-14.492, 27)-(-5.872, 27) reference; L2 (-14.492, 14.985)-(-14.492, 27) reference; L3 (-24, 1.731)-(-14.492, 14.985) reference; L4 (-5.872, 27)-(-14.492, 14.985); 1 further point
  constraints: 2 end point, 1 collinear
extrude "Extrusion101" cut sketch "Sketch101" distance "d213" = 4; taper "d214" = 0 deg
sketch "Sketch102"
  geometry: L1 (4, 33)-(4, 57) reference; L2 (0.641, 33)-(4, 33) reference; L3 (0.641, 30)-(0.641, 33) reference; L4 (0.641, 30)-(6, 30) reference; L5 (6, 30)-(6, 57) reference; L6 (6, 57)-(4, 57) reference; 1 further point
extrude "Extrusion102" join sketch "Sketch102" distance "d215" = 3; taper "d216" = 0 deg
sketch "Sketch103"
  geometry: L1 (0, 0.307)-(3, 0.307) reference; L2 (0, 0.307)-(0, 0) reference; L3 (3, 0)-(0, 0) reference; L4 (3, 0.307)-(3, 0) reference; 1 further point
extrude "Extrusion103" join sketch "Sketch103" distance "d217" = 0.5; taper "d218" = 0 deg
chamfer "Chamfer1" distance "d219" = 5; stored, may be unused: second distance "d220" = 2, angle "d221" = 45 deg
chamfer "Chamfer2" distance "d222" = 2; stored, may be unused: second distance "d223" = 2, angle "d224" = 45 deg
sketch "Sketch104"
  geometry: L1 (76.324, 26.315)-(76.324, 0) reference; L2 (9, 60.457)-(9, 0); L3 (10, 0)-(10, 59.95); L4 (18, 0)-(18, 55.893); L5 (19, 0)-(19, 55.386); L6 (26.598, 0)-(26.598, 51.533); L7 (27.598, 0)-(27.598, 51.026); L8 (35, 0)-(35, 47.272); L9 (36, 0)-(36, 46.765); L10 (43.939, 0)-(43.939, 42.739); L11 (44.939, 0)-(44.939, 42.231); L12 (52, 0)-(52, 38.65); L13 (53, 0)-(53, 38.143); L14 (60.464, 0)-(60.464, 34.358); L15 (61.464, 0)-(61.464, 33.851); L16 (68.598, 0)-(68.598, 30.233); L17 (69.598, 0)-(69.598, 29.726); L18 (10, 14.863)-(10, 6); L19 (18, 6)-(18, 14.863); L20 (18, 19.072)-(18, 23.382); L21 (10, 23.382)-(10, 19.072); L22 (10, 32.511)-(10, 42.231); L23 (18, 42.231)-(18, 32.511); L24 (18, 48)-(18, 51.533); L25 (10, 51.533)-(10, 48); L26 (26.598, 45)-(26.598, 41); L27 (19, 41)-(19, 45); L28 (35, 21.227)-(35, 16.925); L29 (27.598, 16.925)-(27.598, 21.227); L30 (35, 5)-(35, 9); L31 (27.598, 9)-(27.598, 5); L32 (43.939, 36)-(43.939, 32); L33 (36, 32)-(36, 36); L34 (43.939, 10.431)-(43.939, 6); L35 (36, 6)-(36, 10.431); L36 (52, 21.116)-(52, 25.513); L37 (44.939, 25.513)-(44.939, 21.116); L38 (60.464, 14.863)-(60.464, 10.431); L39 (53, 10.431)-(53, 14.863); L40 (53, 27.693)-(53, 32); L41 (60.464, 32)-(60.464, 27.693); L42 (68.598, 25.513)-(68.598, 29); L43 (61.464, 29)-(61.464, 25.513); L44 (76.324, 6)-(76.324, 12.647); L45 (69.598, 12.647)-(69.598, 6); L46 (69.598, 21.116)-(69.598, 23.314); L47 (76.324, 23.314)-(76.324, 21.116); L48 (61.464, 5)-(61.464, 12.647); L49 (68.598, 12.647)-(68.598, 5); L50 (68.598, 16.925)-(68.598, 21.116); L51 (61.464, 21.116)-(61.464, 16.925); L52 (53, 23.314)-(53, 18); L53 (60.464, 18)-(60.464, 23.314); L54 (52, 5)-(52, 14.863); L55 (44.939, 14.863)-(44.939, 5); L56 (44.939, 29)-(44.939, 38.143); L57 (52, 38.143)-(52, 29); L58 (27.598, 38.143)-(27.598, 27.256); L59 (35, 27.256)-(35, 38.143); L60 (35, 43)-(35, 47.272); L61 (27.598, 47.272)-(27.598, 43); L62 (43.939, 29)-(43.939, 14.863); L63 (36, 14.863)-(36, 29); L64 (19, 11)-(19, 25)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; 2 further points
  constraints: 176 end point, 59 point on line, 47 parallel, 7 collinear, 4 midpoint, 1 perpendicular, 17 other
extrude "Extrusion104" cut sketch "Sketch104" distance "d225" = 0.5; taper "d226" = 0 deg
sketch "Sketch105"
  geometry: L1 (0, 0)-(65.022, 0) reference; L2 (65.022, -9)-(4.567, -9); L3 (65.022, -10)-(5.074, -10); L4 (65.022, -18)-(9.133, -18); L5 (65.022, -19)-(9.641, -19); L6 (65.022, -26.603)-(13.499, -26.603); L7 (65.022, -27.599)-(14.004, -27.599); L8 (65.022, -35)-(17.759, -35); L9 (65.022, -36)-(18.266, -36); L10 (65.022, -44)-(22.326, -44); L11 (65.022, -45)-(22.833, -45); L12 (65.022, -52)-(26.385, -52); L13 (65.022, -53)-(26.892, -53); L14 (65.022, -60.353)-(30.623, -60.353); L15 (65.022, -61.514)-(31.212, -61.514); L16 (65.022, -68.562)-(34.789, -68.562); L17 (65.022, -69.392)-(35.209, -69.392); 3 further points
  constraints: 32 end point, 16 parallel, 34 other
extrude "Extrusion105" cut sketch "Sketch105" distance "d227" = 0.5; taper "d228" = 0 deg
